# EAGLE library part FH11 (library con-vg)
Fem. Connector H11 Solder http://www.erni.com/DB/PDF-Drawing/DIN/424654.pdf
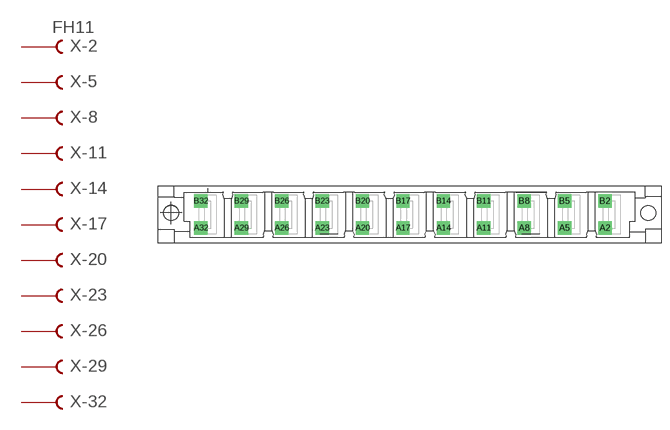
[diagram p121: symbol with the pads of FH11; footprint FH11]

Designator prefix X; gates -2=FVAL2 -5=FEM2 -8=FEM2 -11=FEM2 -14=FEM2 -17=FEM2 -20=FEM2 -23=FEM2 -26=FEM2 -29=FEM2 -32=FEM2

## FH11  [FH11]
A2  -2:A  pas
A5  -5:A  pas
A8  -8:A  pas
A11  -11:A  pas
A14  -14:A  pas
A17  -17:A  pas
A20  -20:A  pas
A23  -23:A  pas
A26  -26:A  pas
A29  -29:A  pas
A32  -32:A  pas
B2  -2:B  pas
B5  -5:B  pas
B8  -8:B  pas
B11  -11:B  pas
B14  -14:B  pas
B17  -17:B  pas
B20  -20:B  pas
B23  -23:B  pas
B26  -26:B  pas
B29  -29:B  pas
B32  -32:B  pas

## Footprint FH11 (pad centres in mm)
Fem. Connector H 11 Solder STVH11, 424654 Source: http://www.erni.com/DB/PDF-Drawing/DIN/424654.pdf
drill 1 pad 2.5 square: A2 38.1,-2.54; A5 30.48,-2.54; A8 22.86,-2.54; A11 15.24,-2.54; A14 7.62,-2.54; A17 0,-2.54; A20 -7.62,-2.54; A23 -15.24,-2.54; A26 -22.86,-2.54; A29 -30.48,-2.54; A32 -38.1,-2.54; B2 38.1,2.54; B5 30.48,2.54; B8 22.86,2.54; B11 15.24,2.54; B14 7.62,2.54; B17 0,2.54; B20 -7.62,2.54; B23 -15.24,2.54; B26 -22.86,2.54; B29 -30.48,2.54; B32 -38.1,2.54
hole 2.8 at -43.73,0.3
hole 2.8 at 46.27,0.3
